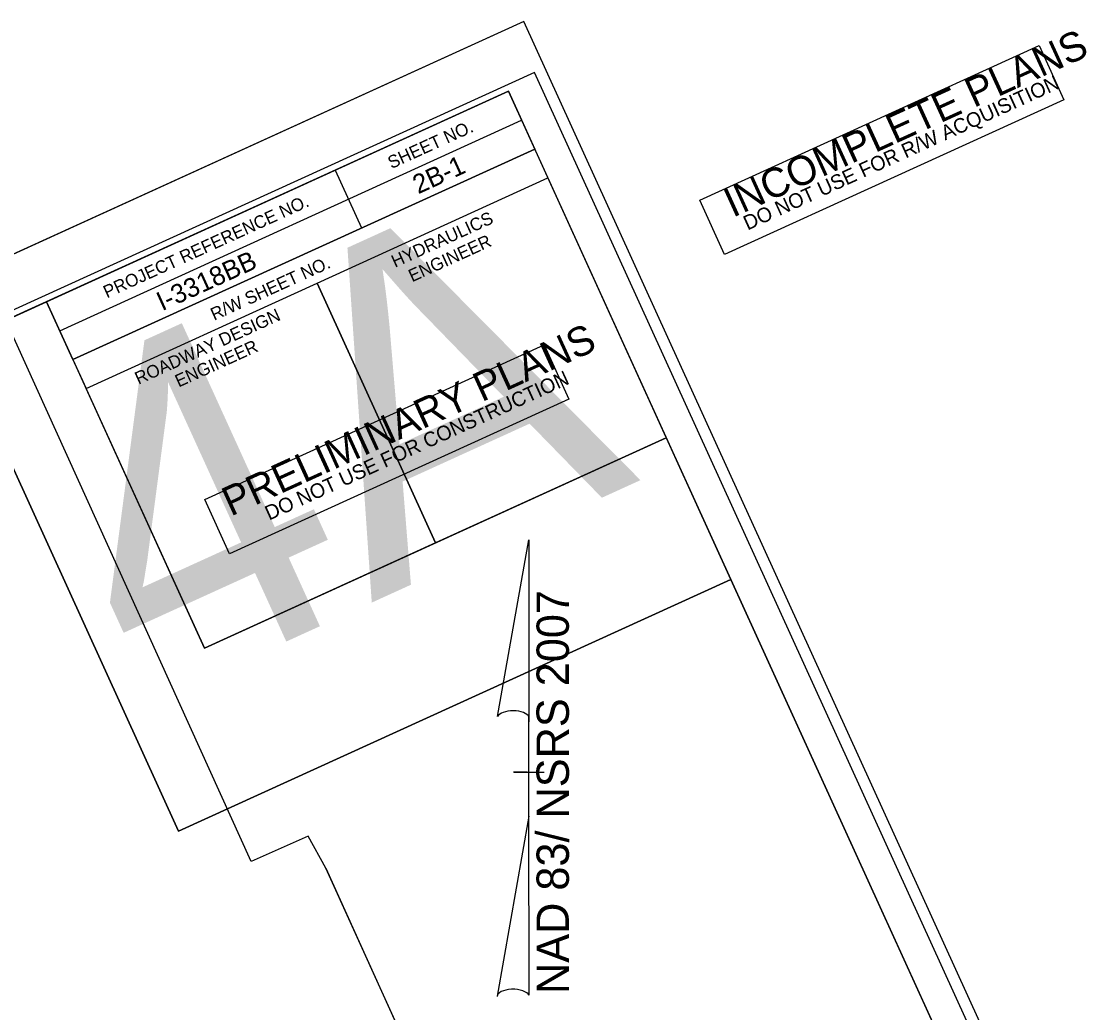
# Model space of a CAD drawing. Extents: x 2246788 to 2248774, y 662010 to 663780.
# Drawn here: x 2248121.7 to 2248544.3, y 663314.1 to 663704.8 of the extents above; entities that cross this region are included whole.
import ezdxf

# ---------------------------------------------------------------- set-up
doc = ezdxf.new("R2010")
doc.units = 0
for name, color, linetype in [('Matchline', 7, 'Continuous'), ('Prop North Arrow NAD83 for Plan Sheets CELL', 7, 'Continuous'), ('Sheet Clip Boundary CELL', 7, 'Continuous'), ('Sheet Cutting Line CELL', 7, 'Continuous'), ('Sheet Data Field CELL', 7, 'Continuous'), ('Sheet Plan CELL', 7, 'Continuous'), ('Sheet Plan Layout CELL', 7, 'Continuous'), ('Sheet Plot Border Inside CELL', 7, 'Continuous'), ('Sheet Plot Border Outside CELL', 7, 'Continuous'), ('Sheet Sticker Incomplete CELL', 7, 'Continuous'), ('Sheet Sticker Preliminary CELL', 7, 'Continuous')]:
    doc.layers.add(name, color=color, linetype=linetype)

msp = doc.modelspace()

# ---------------------------------------------------------------- linework, layer by layer
at = {"layer": 'Matchline'}
msp.add_line((2248241.67, 663371.06), (2248527.99, 662740.75), dxfattribs=at)
at = {"layer": 'Prop North Arrow NAD83 for Plan Sheets CELL'}
for p, q in [((2248309.36, 663430.89), (2248321.66, 663500.41)), ((2248321.73, 663500.41), (2248321.66, 663500.41)), ((2248321.73, 663500.41), (2248321.66, 663500.41)), ((2248321.73, 663500.41), (2248321.73, 663428.71)), ((2248321.73, 663391.51), (2248321.73, 663430.81)), ((2248321.73, 663428.71), (2248321.73, 663430.74)), ((2248315.73, 663408.91), (2248315.66, 663408.91)), ((2248321.06, 663408.91), (2248315.73, 663408.91)), ((2248315.81, 663408.91), (2248327.81, 663408.91)), ((2248321.73, 663391.51), (2248309.21, 663320.64)), ((2248321.81, 663320.94), (2248321.73, 663391.51))]:
    msp.add_line(p, q, dxfattribs=at)
for centre, start_param, end_param in [((2248315.56, 663430.14), 0.216388, 2.908219), ((2248315.56, 663320.39), 0.201328, 3.141593)]:
    msp.add_ellipse(centre, major_axis=(6.35, -0.05), ratio=0.461098, start_param=start_param, end_param=end_param, dxfattribs=at)
at = {"layer": 'Sheet Clip Boundary CELL'}
msp.add_lwpolyline([(2248573.04, 662641.59), (2248489.82, 662824.78), (2248241.67, 663371.06), (2248234.7, 663383.7), (2248212.22, 663373.68), (2248115.54, 663587.01), (2247008.72, 663082.61), (2247356.34, 662320.42), (2247308.04, 662298.42), (2247341.49, 662224.75), (2247444.44, 662127.31)], close=True, dxfattribs=at)
at = {"layer": 'Sheet Cutting Line CELL'}
msp.add_line((2248319.81, 663704.79), (2246787.87, 663006.71), dxfattribs=at)
at = {"layer": 'Sheet Plan CELL'}
for p, q in [((2248136.81, 663582.91), (2248318.86, 663665.85)), ((2248142.02, 663571.51), (2248324.04, 663654.48)), ((2248142.02, 663571.51), (2248324.04, 663654.48)), ((2248245.41, 663646.11), (2248255.82, 663623.38)), ((2248238.24, 663601.63), (2248284.89, 663499.3)), ((2248142.02, 663571.51), (2248147.2, 663560.15))]:
    msp.add_line(p, q, dxfattribs=at)
for points in [[(2248313.69, 663677.29), (2246948.69, 663055.28), (2247384.08, 662099.81), (2248749.06, 662721.8)], [(2248131.62, 663594.34), (2248313.69, 663677.29), (2248324.04, 663654.48), (2248142.02, 663571.51)], [(2248238.24, 663601.63), (2248329.22, 663643.1), (2248375.89, 663540.73), (2248284.9, 663499.25)], [(2248147.2, 663560.15), (2248238.24, 663601.63), (2248284.9, 663499.25), (2248193.86, 663457.79)], [(2247384.08, 662099.81), (2246948.68, 663055.25), (2248131.62, 663594.34), (2248193.86, 663457.79), (2248375.89, 663540.73), (2248749.06, 662721.8)]]:
    msp.add_lwpolyline(points, close=True, dxfattribs=at)
at = {"layer": 'Sheet Plan Layout CELL'}
for points in [[(2248183.64, 663385.62), (2248401.37, 663484.84), (2248313.7, 663677.29), (2248095.94, 663578.07)], [(2246948.68, 663055.25), (2247384.08, 662099.81), (2248749.05, 662721.8), (2248401.35, 663484.83), (2248183.64, 663385.62), (2248095.94, 663578.07)]]:
    msp.add_lwpolyline(points, close=True, dxfattribs=at)
at = {"layer": 'Sheet Plot Border Inside CELL'}
msp.add_lwpolyline([(2247245.45, 662033.88), (2248761.46, 662724.71), (2248324.01, 663684.73), (2246807.99, 662993.9)], close=True, dxfattribs=at)
at = {"layer": 'Sheet Plot Border Outside CELL'}
msp.add_lwpolyline([(2247241.92, 662010.29), (2248773.86, 662708.37), (2248319.81, 663704.79), (2246787.87, 663006.71)], close=True, dxfattribs=at)
at = {"layer": 'Sheet Sticker Incomplete CELL'}
msp.add_lwpolyline([(2248398.8, 663612.98), (2248389.06, 663634.36), (2248522.82, 663695.32), (2248532.57, 663673.94)], close=True, dxfattribs=at)
at = {"layer": 'Sheet Sticker Preliminary CELL'}
msp.add_lwpolyline([(2248203.78, 663494.93), (2248194.04, 663516.32), (2248327.8, 663577.27), (2248337.55, 663555.89)], close=True, dxfattribs=at)

# ---------------------------------------------------------------- texts
at = {"layer": 'Prop North Arrow NAD83 for Plan Sheets CELL'}
msp.add_text('NAD 83/ NSRS 2007', height=12.75, rotation=90, dxfattribs=at).set_placement((2248337.51, 663321.46))
at = {"layer": 'Sheet Data Field CELL'}
for s, p in [('2B-1', (2248278.12, 663636.63)), ('I-3318BB', (2248177.16, 663590.56))]:
    msp.add_text(s, height=7.5, rotation=24.4979, dxfattribs=at).set_placement(p)
at = {"layer": 'Sheet Plan CELL'}
for s, height, p in [('SHEET NO.', 5, (2248267.56, 663646.57)), ('PROJECT REFERENCE NO.', 5.0001, (2248155.44, 663595.6)), ('HYDRAULICS', 5, (2248268.98, 663607.64)), ('ENGINEER', 5, (2248275.71, 663601.96)), ('R/W SHEET NO.', 5.0001, (2248197.7, 663586.78)), ('ROADWAY DESIGN', 5.0001, (2248167.86, 663561.54)), ('ENGINEER', 5, (2248183.71, 663560.48))]:
    msp.add_text(s, height=height, rotation=24.4979, dxfattribs=at).set_placement(p)
at = {"layer": 'Sheet Plan Layout CELL'}
msp.add_text('4A', height=131.25, rotation=24.4979, dxfattribs=at).set_placement((2248170.68, 663435.11))
at = {"layer": 'Sheet Sticker Incomplete CELL'}
for s, height, p in [('INCOMPLETE PLANS', 11.52, (2248402.09, 663627.34)), ('DO NOT USE FOR R/W ACQUISITION', 5.76, (2248407.93, 663622.36))]:
    msp.add_text(s, height=height, rotation=24.4979, dxfattribs=at).set_placement(p)
at = {"layer": 'Sheet Sticker Preliminary CELL'}
for s, height, p in [('PRELIMINARY PLANS', 11.52, (2248204.24, 663509.59)), ('DO NOT USE FOR CONSTRUCTION', 5.76, (2248219.36, 663508.02))]:
    msp.add_text(s, height=height, rotation=24.4979, dxfattribs=at).set_placement(p)

doc.saveas('drawing.dxf')
